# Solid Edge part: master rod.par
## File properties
Author: Administrator
Template: normal.par
Last saved by: CADCIM
Revision: 17
Application: Solid Edge
Density: 0.00000775 kg/mm^3
Accuracy: 0.99
Material: Stainless steel
Face Style: Steel
Fill Style: ANSI32(Steel)
Virtual Style: Stainless steel
Categorization: Metals\Steel
LibraryName: Materials
Coef. of Thermal Exp: 1.6e-05
Thermal Conductivity: 17.0
Specific Heat: 502.0
Modulus of Elasticity: 193053196000.0
Poisson's Ratio: 0.29
Yield Stress: 310264065.0
Ultimate Stress: 641212401.0
Elongation: 0.0
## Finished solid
Body 1: solid body, 60 faces, 148 edges, 80 vertices.
  Faces by surface: cylinder 42, plane 18
  Edges by curve: circle 78, line 58, ellipse 12
Bounding box of the edges (mm): 320.500 x 112.000 x 70.000, from (-118.4884, -56, -35) to (202.0116, 56, 35).
Cylindrical faces by radius (mm): R5 x8, R6 x4, R12 x1, R13 x8, R17.5 x1, R26 x1, R31.5 x3, R35 x2, R72.03 x8, R78 x4, R207.0766 x1, R207.2725 x1
Planar faces by outward normal: +y 2, +z 5, -y 2, -z 5, oblique 4
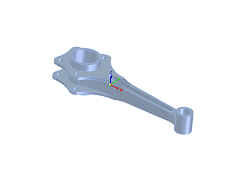
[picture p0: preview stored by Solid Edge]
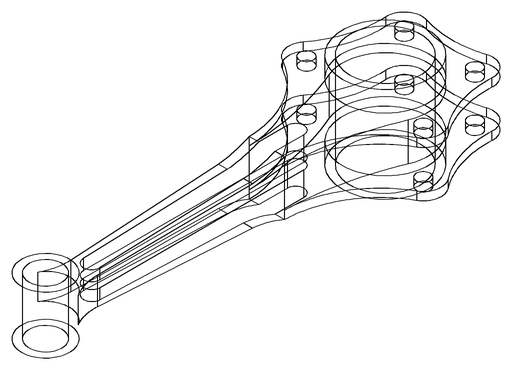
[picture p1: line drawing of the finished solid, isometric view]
